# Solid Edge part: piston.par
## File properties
Author: Deepak Maini
Template: normal.par
Last saved by: CADCIM
Revision: 9
Application: Solid Edge
Accuracy: 0.99
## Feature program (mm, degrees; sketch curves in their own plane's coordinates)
sketch for "unnamed RevolvedProtrusion 1" plane through (0, 0, 0) normal (0, -1, 0) x-axis (1, 0, 0)
  line (0, 27.2252) -> (0, 16)
  line (0, 16) -> (37, 16)
  line (37, 16) -> (37, -4)
  line (37, -4) -> (38.5, -4)
  line (38.5, -4) -> (38.5, -34)
  line (38.5, -34) -> (37, -34)
  line (37, -34) -> (37, -46)
  line (46.5, -46) -> (37, -46)
  line (46.5, -41) -> (46.5, -46)
  line (42.5, -41) -> (46.5, -41)
  line (42.5, -39) -> (42.5, -41)
  line (46.5, -39) -> (42.5, -39)
  line (46.5, 0) -> (46.5, -39)
  line (42.5, 0) -> (46.5, 0)
  line (42.5, 3) -> (42.5, 0)
  line (46.5, 3) -> (42.5, 3)
  line (46.5, 5) -> (46.5, 3)
  line (42.5, 5) -> (46.5, 5)
  line (42.5, 8) -> (42.5, 5)
  line (46.5, 8) -> (42.5, 8)
  line (46.5, 10) -> (46.5, 8)
  line (42.5, 10) -> (46.5, 10)
  line (42.5, 13) -> (42.5, 10)
  line (46.5, 13) -> (42.5, 13)
  line (46.5, 15) -> (46.5, 13)
  line (42.5, 15) -> (46.5, 15)
  line (42.5, 18) -> (42.5, 15)
  line (46.5, 18) -> (42.5, 18)
  line (46.5, 20) -> (46.5, 18)
  arc centre (-5.5431, -161.6935) radius 189 from (0, 27.2252) to (46.5, 20) cw
revolve "unnamed RevolvedProtrusion 1" add full turn 360 deg
sketch for "unnamed Protrusion 1" plane through (0, 25, 0) normal (0, -1, 0) x-axis (1, 0, 0)
  circle centre (0, -19.5) radius 19
extrude "unnamed Protrusion 1" add through along -normal
mirror "unnamed Mirror 1" of "unnamed Protrusion 1" about plane through (0, 0, 0) normal (0, -1, 0)
extrude "unnamed Protrusion 2" add through
sketch for "unnamed RevolvedCutout 1" plane through (0, 0, 0) normal (1, 0, 0) x-axis (0, 1, 0)
revolve "unnamed RevolvedCutout 1" cut full turn 360 deg about sketch line (-52.4217, -19) -> (59.5434, -19)
mirror "unnamed Mirror 2" of "unnamed RevolvedCutout 1"
pattern "unnamed Pattern 1"
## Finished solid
Body 1: solid body, 42 faces, 58 edges, 16 vertices.
  Faces by surface: cylinder 21, plane 20, torus 1
  Edges by curve: circle 40, intersection 10, line 8
Bounding box of the edges (mm; curved faces can reach further): 93.000 x 93.000 x 66.000, from (-46.5, -46.5, -46) to (46.5, 46.5, 20).
Cylindrical faces by radius (mm): R10 x2, R15 x2, R19 x2, R37 x2, R38.5 x2, R42.5 x5, R46.5 x6
Toroidal faces (ring radius, tube radius in mm): R-5.5431 r189 x1
Planar faces by outward normal: +y 2, +z 7, -y 2, -z 9
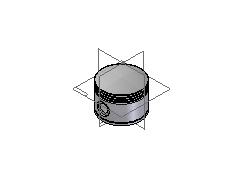
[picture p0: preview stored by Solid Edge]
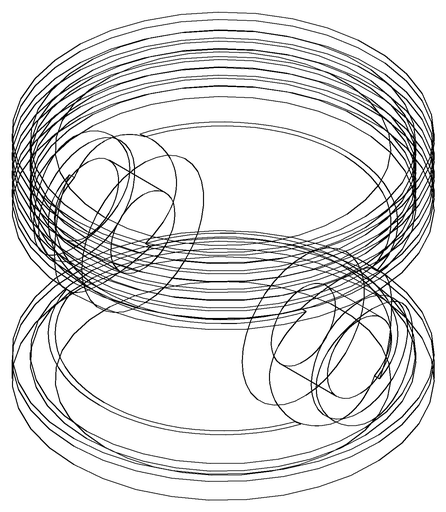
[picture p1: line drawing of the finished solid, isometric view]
